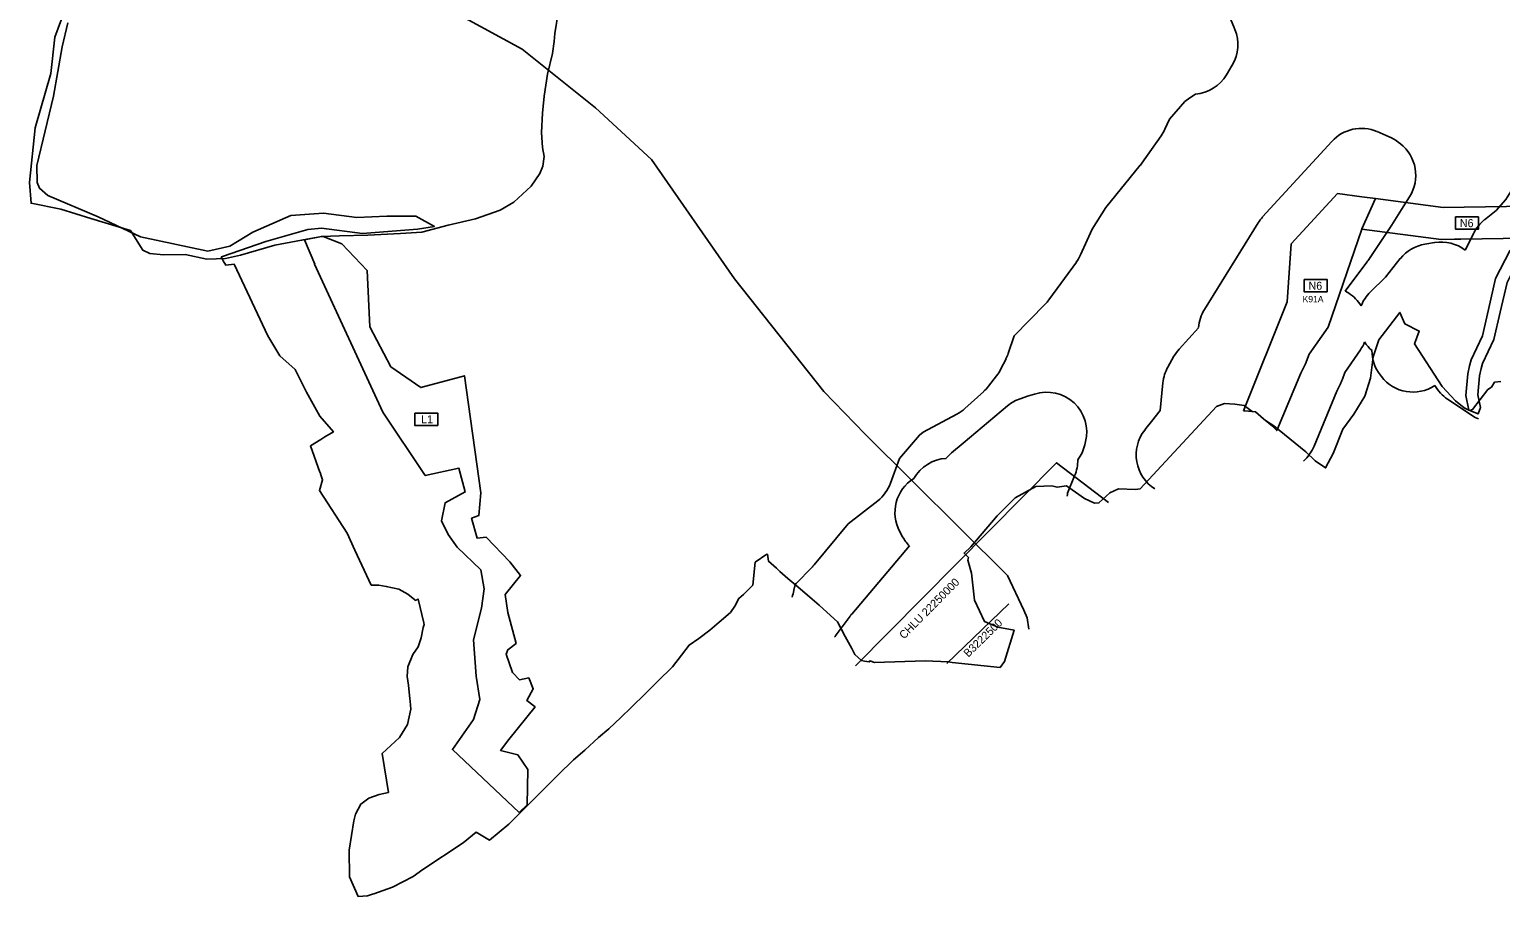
# Model space of a CAD drawing. Extents: x -547623 to -532764, y -1096714 to -1086523.
# Drawn here: x -547623 to -545785, y -1096380 to -1095297 of the extents above; entities that cross this region are included whole.
import ezdxf

# ---------------------------------------------------------------- set-up
doc = ezdxf.new("R2010")
doc.units = 0
for name, color, linetype in [('Vrstva 22', 7, 'Continuous'), ('Vrstva 23', 7, 'Continuous'), ('Vrstva 25', 7, 'Continuous'), ('Vrstva 27', 7, 'Continuous'), ('Vrstva 28', 7, 'Continuous'), ('Vrstva 33', 7, 'Continuous'), ('Vrstva 36', 7, 'Continuous'), ('Vrstva 40', 7, 'Continuous'), ('Vrstva 41', 7, 'Continuous')]:
    doc.layers.add(name, color=color, linetype=linetype)

msp = doc.modelspace()

# ---------------------------------------------------------------- linework, layer by layer
at = {"layer": 'Vrstva 22'}
for points in [[(-546374.7, -1096045.9), (-546376.9, -1096031.7), (-546380.9, -1096022.4), (-546401.2, -1095979), (-546579.1, -1095802.5), (-546630.7, -1095748.9), (-546742.6, -1095608.3), (-546846, -1095459), (-546916.2, -1095394.5), (-547007.9, -1095321.1), (-547083.5, -1095279.9), (-547200.4, -1095263.8), (-547344.8, -1095240.9), (-547527.1, -1095243.1), (-547535, -1095243.2), (-547551.1, -1095243.9), (-547564.5, -1095244.5), (-547572, -1095244.8), (-547573.4, -1095244.8)], [(-547575.4, -1095288.3), (-547582.5, -1095318.3), (-547593.3, -1095380.2), (-547614, -1095466.7), (-547613.8, -1095487.8), (-547610.9, -1095495.1), (-547600.3, -1095504.3), (-547537.7, -1095530.8), (-547484.6, -1095555.9), (-547400.5, -1095573.6), (-547373.2, -1095567.5), (-547344.1, -1095549.8), (-547296.7, -1095529.3), (-547256, -1095526.1), (-547214.4, -1095531.5), (-547177, -1095529.9), (-547140.8, -1095529.9), (-547117.3, -1095542.8), (-547138.4, -1095546.2), (-547207.2, -1095551.5), (-547258.4, -1095545.1), (-547275.6, -1095546.8), (-547328, -1095561.5), (-547382.2, -1095580.3), (-547383.7, -1095580.9), (-547381.2, -1095585.7), (-547378, -1095591.3), (-547367.7, -1095589.8), (-547325.4, -1095679.6), (-547310.7, -1095704.4), (-547291.2, -1095721.7), (-547277.2, -1095749.8), (-547260.6, -1095779.7), (-547243.6, -1095799.5), (-547254.2, -1095805.9), (-547259.2, -1095809), (-547272.4, -1095817), (-547260.6, -1095849.7), (-547259.5, -1095851.5), (-547259.8, -1095851.9), (-547257.1, -1095859.5), (-547261.1, -1095872.9), (-547226.5, -1095925.9), (-547217, -1095947.4), (-547196.4, -1095990.9), (-547186.8, -1095991.2), (-547177.5, -1095992.7), (-547162, -1095995.9), (-547150.5, -1096002.1), (-547141.9, -1096009.2), (-547141.4, -1096010.1), (-547137.7, -1096008.4), (-547130.5, -1096038.3), (-547130.5, -1096038.5), (-547130, -1096040.2), (-547131.5, -1096043.9), (-547133.9, -1096056.9), (-547137.8, -1096067.9), (-547144.5, -1096077.5), (-547150.5, -1096093.1), (-547151.4, -1096105), (-547149.9, -1096115.8), (-547148.1, -1096133), (-547147.5, -1096135.5), (-547147.8, -1096136), (-547146.7, -1096146.2), (-547151.1, -1096165.1), (-547161.2, -1096181.3), (-547182.6, -1096201.3), (-547174.8, -1096250.1), (-547186.6, -1096252.7), (-547199.2, -1096257.2), (-547209.2, -1096264.5), (-547216, -1096277.1), (-547218.1, -1096285.5), (-547223.9, -1096322.2), (-547223.7, -1096355.7), (-547212.5, -1096380.2), (-547201.1, -1096379.3), (-547194.6, -1096377.2), (-547193.1, -1096376.7), (-547169.9, -1096368.3), (-547143.8, -1096355.1), (-547131.7, -1096346.5), (-547081.4, -1096313), (-547065.1, -1096299.8), (-547048.6, -1096309.6), (-547024.3, -1096289.9), (-547015.1, -1096280.6), (-547000.8, -1096266.1), (-546979.1, -1096244.1), (-546962.9, -1096228), (-546943.7, -1096209.1), (-546929.6, -1096197.1), (-546912.2, -1096181.6), (-546899.6, -1096170.5), (-546884.6, -1096156.4), (-546871.6, -1096143.9), (-546853.8, -1096126.4), (-546838.1, -1096111.2), (-546819.9, -1096092.9), (-546808.6, -1096078.4), (-546799.2, -1096065.9), (-546787.2, -1096057.5), (-546773.2, -1096047.4), (-546761.4, -1096037.3), (-546747.4, -1096025), (-546742.2, -1096017.1), (-546737, -1096007.7), (-546731.3, -1096002.8), (-546726.2, -1095997.6), (-546719.7, -1095991.1), (-546716.8, -1095962.5), (-546702, -1095952.4), (-546702, -1095953.1), (-546701.2, -1095952.4), (-546699.8, -1095961.1), (-546690.1, -1095969.8), (-546685.7, -1095973.8), (-546675.9, -1095982.6), (-546666, -1095991.2), (-546654.6, -1096000.6), (-546645.2, -1096008.7), (-546636.7, -1096015.9), (-546626.9, -1096024.7), (-546613.9, -1096036.9), (-546604.1, -1096055.1), (-546595.8, -1096070.2), (-546592.1, -1096077.6), (-546583.8, -1096085.2), (-546580, -1096086), (-546574.1, -1096087), (-546573.5, -1096085.7), (-546567.4, -1096087.7), (-546504, -1096085.8), (-546474.9, -1096086.8), (-546470.6, -1096087.6), (-546450.5, -1096089.6), (-546410.5, -1096093.9), (-546404.9, -1096086.5), (-546393, -1096047.2), (-546413.3, -1096043.7), (-546430.1, -1096036.3), (-546442.4, -1096010), (-546446.5, -1095976.1), (-546450.7, -1095959.8), (-546450, -1095956.6), (-546455.5, -1095951), (-546447.3, -1095943.2), (-546447.3, -1095943.1), (-546414.1, -1095904.3), (-546391.6, -1095882.1), (-546366.1, -1095867.9), (-546346.1, -1095867), (-546339.4, -1095868.8), (-546327.8, -1095866.9), (-546305, -1095882.6), (-546292.6, -1095888.6), (-546287.2, -1095888.2), (-546273.4, -1095875.8), (-546262.8, -1095870.7), (-546241.5, -1095871.7), (-546235.6, -1095870.7), (-546140, -1095767.7), (-546130.1, -1095764.1), (-546117.3, -1095764.8), (-546105.7, -1095766.6), (-546095.7, -1095774.1), (-546091.3, -1095774.5), (-546081.4, -1095783), (-546078.8, -1095785.3), (-546068.7, -1095791.9), (-546028.6, -1095824.3), (-546016.7, -1095835.7), (-546003.8, -1095844.6), (-545994.6, -1095826.5), (-545982.2, -1095796), (-545968.5, -1095777.4), (-545954.7, -1095754.8), (-545947.9, -1095732.5), (-545944.6, -1095705.6), (-545937.3, -1095684.3), (-545911.1, -1095650.3), (-545905, -1095664.5), (-545886.9, -1095673.6), (-545892.7, -1095689.4), (-545858.2, -1095742.8), (-545841.6, -1095760.7), (-545830.6, -1095769.5), (-545827.4, -1095771.2), (-545823.7, -1095772.7), (-545820.2, -1095771.6), (-545801.1, -1095746.5), (-545796.7, -1095743.7), (-545793, -1095737.5), (-545784.9, -1095736.4)]]:
    msp.add_lwpolyline(points, dxfattribs=at)
at = {"layer": 'Vrstva 23'}
for p, q in [((-546127.7, -1095353.3), (-546120.5, -1095341.1)), ((-546233.4, -1095463.7), (-546209.4, -1095429.7)), ((-545996.1, -1095436.6), (-546082.5, -1095531)), ((-545924.4, -1095430.7), (-545939.6, -1095424.3)), ((-545910.4, -1095439.5), (-545913.2, -1095437.3)), ((-546088, -1095538.4), (-546155.3, -1095646.6)), ((-545950.7, -1095585.2), (-545922.3, -1095542.8)), ((-545877.3, -1095564.6), (-545879.8, -1095565)), ((-545867.6, -1095563), (-545877.2, -1095564.6)), ((-545818.6, -1095551), (-545829.3, -1095572.4)), ((-546349.7, -1095634.6), (-546315.3, -1095587.5)), ((-546162.7, -1095669.3), (-546186.9, -1095696.1)), ((-546410.1, -1095721.7), (-546403.2, -1095708.4)), ((-546193.3, -1095705), (-546201, -1095718.5)), ((-546425, -1095742.5), (-546414.9, -1095729.4)), ((-545935.4, -1095728.8), (-545934.2, -1095730.5)), ((-546454.5, -1095770.2), (-546431.1, -1095749.1)), ((-546376.2, -1095755), (-546384.4, -1095757.6)), ((-546367.5, -1095752.3), (-546376.2, -1095755)), ((-545851.6, -1095758.5), (-545820.7, -1095779.1)), ((-546304.7, -1095815.7), (-546303.8, -1095811.7)), ((-546326.4, -1095876), (-546317.5, -1095854.5)), ((-546535.8, -1095924.4), (-546532.4, -1095930.6)), ((-546523.7, -1095942.1), (-546596, -1096027.1)), ((-546665.4, -1095988.8), (-546645.8, -1095968.9)), ((-546668.1, -1095997.5), (-546666.8, -1095990.1)), ((-546598.1, -1096029.8), (-546615.4, -1096053.3)), ((-546616.8, -1096055.3), (-546617.3, -1096056))]:
    msp.add_line(p, q, dxfattribs=at)
for points in [[(-546117.2, -1095296.6), (-546118.5, -1095293.5), (-546126, -1095275.3), (-546121.3, -1095268.9)], [(-546204.6, -1095421.4), (-546199, -1095408.9), (-546179.7, -1095386.5), (-546173.7, -1095382.2), (-546166.5, -1095377.6)], [(-546310, -1095578.4), (-546295.7, -1095546.3), (-546278.3, -1095519.3), (-546235.4, -1095466.2)], [(-545753.9, -1095462.4), (-545768.1, -1095492.4), (-545778.6, -1095509), (-545790.8, -1095522.7), (-545805.2, -1095534.4)], [(-545921.5, -1095541.5), (-545909, -1095521.5), (-545899, -1095505.9)], [(-545910.5, -1095583), (-545929.2, -1095606.2), (-545948.1, -1095624.8)], [(-545975, -1095626.3), (-545979, -1095623.8), (-545979.3, -1095623.6), (-545952.2, -1095587.3)], [(-546400.3, -1095701.5), (-546393, -1095679.6), (-546354.3, -1095640.1)], [(-545982.8, -1095733.7), (-545979.9, -1095725.4), (-545960.4, -1095696.9)], [(-546207.2, -1095738.1), (-546210.7, -1095772.8), (-546221.4, -1095786.7), (-546228.3, -1095795.4), (-546229.8, -1095797.3)], [(-546018.1, -1095817.2), (-545990, -1095748.7), (-545985.4, -1095739.5)], [(-546401.5, -1095767.1), (-546456.7, -1095813.6), (-546471.2, -1095825.8)], [(-546547.5, -1095863.7), (-546536.1, -1095832.8), (-546511.4, -1095803.5), (-546506.7, -1095799.7), (-546464.5, -1095777.2)], [(-546642.9, -1095965.7), (-546600.3, -1095914.5), (-546563.5, -1095885.7)]]:
    msp.add_lwpolyline(points, dxfattribs=at)
for centre, start, end in [((-546163.5, -1095315.6), 329.3339, 22.2778), ((-546170.8, -1095327.8), 274.8993, 329.3339), ((-545959.2, -1095470.3), 66.9745, 137.5574), ((-546250.2, -1095400.8), 324.7281, 335.751), ((-545944, -1095476.8), 52.0686, 66.9745), ((-545941.2, -1095478.9), 327.4259, 52.0686), ((-546274.2, -1095434.8), 321.0365, 324.7281), ((-546045.6, -1095564.8), 137.5574, 148.1433), ((-545963.9, -1095515), 326.2197, 327.9921), ((-545773.9, -1095573.3), 128.7931, 153.4624), ((-545871.5, -1095614.3), 99.4623, 141.1731), ((-545869.1, -1095613.9), 99.3946, 99.4623), ((-545859.4, -1095612.3), 52.9674, 99.3946), ((-546355.7, -1095558), 323.8507, 335.9031), ((-545992.3, -1095557.4), 323.3168, 326.2197), ((-546390.1, -1095605.1), 315.6842, 323.8507), ((-546001.6, -1095668.7), 32.4097, 57.8301), ((-545912.9, -1095660.4), 134.6079, 158.2243), ((-546112.8, -1095673), 148.1433, 175.692), ((-546149.8, -1095729.6), 137.9221, 150.5213), ((-546001.6, -1095668.7), 325.5594, 338.2242), ((-545912.9, -1095660.4), 212.4097, 228.7237), ((-546447.7, -1095685.6), 332.8189, 341.4563), ((-545895.9, -1095698.2), 179.7572, 217.7905), ((-546454.5, -1095698.9), 322.4377, 332.8189), ((-546157.4, -1095743.1), 150.5213, 174.2499), ((-545894.7, -1095699.8), 217.7905, 303.2377), ((-546464.6, -1095712), 312.0508, 322.4377), ((-546352.3, -1095799.9), 346.3398, 107.6583), ((-546029.9, -1095716.8), 332.9792, 340.2804), ((-545823.8, -1095716.9), 209.6577, 236.2928), ((-546488, -1095733.1), 298.0424, 312.0508), ((-546369.2, -1095805.3), 107.6761, 130.1526), ((-546361, -1095802.7), 107.6583, 107.6761), ((-545793, -1095737.5), 236.2928, 246.4945), ((-546190.6, -1095828.3), 141.7032, 238.0572), ((-546353.3, -1095803.9), 322.5105, 346.3398), ((-546064.4, -1095798.3), 310.8902, 337.7348), ((-546474.9, -1095882.5), 93.4027, 150.4797), ((-546439.1, -1095864.1), 130.0137, 140.8733), ((-546363.6, -1095835.2), 337.3868, 1.0949), ((-546492, -1095900.3), 121.8827, 208.758), ((-546594.4, -1095846.3), 308.1387, 339.6598), ((-546376.4, -1095875.5), 355.1232, 359.4282), ((-546488.5, -1095906.6), 208.758, 225.3511), ((-546681.4, -1095933.8), 315.3004, 320.2433), ((-546701, -1095953.6), 313.066, 315.3004), ((-546717.4, -1095988.8), 339.7159, 349.9514), ((-546557.9, -1096059.5), 139.6045, 143.5782), ((-546575.2, -1096083), 143.5782, 146.3614)]:
    msp.add_arc(centre, 50, start, end, dxfattribs=at)
at = {"layer": 'Vrstva 25'}
msp.add_lwpolyline([(-547565.4, -1095235.1), (-547591.5, -1095306.5), (-547596.8, -1095351.7), (-547616.3, -1095419.4), (-547623.4, -1095487.8), (-547621.3, -1095513.9), (-547584, -1095521.3), (-547546.8, -1095532.9), (-547497, -1095547.9), (-547481.9, -1095572.4), (-547472.9, -1095576.5), (-547456.1, -1095578.2), (-547428.9, -1095577.9), (-547401.6, -1095583.7), (-547378.5, -1095583), (-547359.5, -1095578.5), (-547316.7, -1095566.2), (-547283.3, -1095560.1), (-547258.6, -1095555.3), (-547236, -1095554.6), (-547200.7, -1095553.9), (-547159.6, -1095551.5), (-547133.3, -1095549.8), (-547100.1, -1095541.4), (-547066.1, -1095533.4), (-547035.1, -1095522.6), (-547018.1, -1095512.3), (-546996.6, -1095492.5), (-546985.7, -1095476.8), (-546981.8, -1095467.4), (-546980.2, -1095455.4), (-546982.2, -1095444), (-546983.5, -1095425.4), (-546982.3, -1095401.3), (-546980.3, -1095380.1), (-546976.2, -1095352.7), (-546969.7, -1095326.9), (-546967.7, -1095311.8), (-546967.7, -1095311.7), (-546967.7, -1095311.7), (-546966.9, -1095301.9), (-546962.4, -1095273.3)], dxfattribs=at)
at = {"layer": 'Vrstva 27'}
msp.add_lwpolyline([(-547565.4, -1095235.1), (-547591.5, -1095306.5), (-547596.8, -1095351.7), (-547616.3, -1095419.4), (-547623.4, -1095487.8), (-547621.3, -1095513.9), (-547584, -1095521.3), (-547546.8, -1095532.9), (-547497, -1095547.9), (-547481.9, -1095572.4), (-547472.9, -1095576.5), (-547456.1, -1095578.2), (-547428.9, -1095577.9), (-547401.6, -1095583.7), (-547378.5, -1095583), (-547359.5, -1095578.5), (-547316.7, -1095566.2), (-547283.3, -1095560.1), (-547258.6, -1095555.3), (-547236, -1095554.6), (-547200.7, -1095553.9), (-547159.6, -1095551.5), (-547133.3, -1095549.8), (-547100.1, -1095541.4), (-547066.1, -1095533.4), (-547035.1, -1095522.6), (-547018.1, -1095512.3), (-546996.6, -1095492.5), (-546985.7, -1095476.8), (-546981.8, -1095467.4), (-546980.2, -1095455.4), (-546982.2, -1095444), (-546983.5, -1095425.4), (-546982.3, -1095401.3), (-546980.3, -1095380.1), (-546976.2, -1095352.7), (-546969.7, -1095326.9), (-546967.7, -1095311.8), (-546967.7, -1095311.7), (-546967.7, -1095311.7), (-546966.9, -1095301.9), (-546962.4, -1095273.3)], dxfattribs=at)
at = {"layer": 'Vrstva 28'}
for p, q in [((-545958.7, -1095505.7), (-545989, -1095501.7)), ((-546052, -1095636.9), (-546106.6, -1095773.3)), ((-546024.4, -1095702.2), (-546000.8, -1095668.6)), ((-546035, -1095726.3), (-546029, -1095714.5)), ((-546029, -1095714.5), (-546024.4, -1095702.2))]:
    msp.add_line(p, q, dxfattribs=at)
for points in [[(-545989, -1095501.7), (-546046.7, -1095564.7), (-546052, -1095636.9)], [(-546000.8, -1095668.6), (-545958.7, -1095546.1), (-545958.5, -1095545.7), (-545941.5, -1095508), (-545958.7, -1095505.7)], [(-545725, -1095516.9), (-545857.1, -1095519.2), (-545941.5, -1095508), (-545958.5, -1095545.7), (-545958.7, -1095546.1), (-545859.4, -1095559.2), (-545842.8, -1095558.9), (-545834.7, -1095558.8), (-545755.5, -1095557.4), (-545738.9, -1095539.2), (-545725, -1095516.9)], [(-546106.6, -1095773.3), (-546104.7, -1095773.2), (-546091.3, -1095774.5), (-546081.4, -1095783), (-546070.4, -1095792.5), (-546064.8, -1095797.9), (-546035, -1095726.3)]]:
    msp.add_lwpolyline(points, dxfattribs=at)
at = {"layer": 'Vrstva 33'}
for points in [[(-547279.7, -1095559.4), (-547258.6, -1095555.3)], [(-547267, -1095589.9), (-547279.7, -1095559.4)], [(-547258.6, -1095555.3), (-547256.5, -1095555.2), (-547256.3, -1095555.3), (-547233, -1095564.6), (-547201.3, -1095597.9), (-547197.9, -1095668.2), (-547171.8, -1095718.1), (-547134.4, -1095744.1), (-547080, -1095729.4), (-547059.6, -1095875.6), (-547061.9, -1095904), (-547070.9, -1095907.4), (-547064.1, -1095932.3), (-547052.8, -1095931.2), (-547023.3, -1095961.8), (-547009.7, -1095978.8), (-547029, -1096002.6), (-547025.6, -1096025.3), (-547015.4, -1096063.8), (-547025.6, -1096071.7), (-547027.9, -1096077.4), (-547019.9, -1096100.1), (-547010.9, -1096109.2), (-546999.5, -1096106.9), (-546993.9, -1096120.5), (-547001.8, -1096135.2), (-546991.6, -1096143.2), (-547024.5, -1096184), (-547034.7, -1096197.6), (-547013.1, -1096203.2), (-547000.7, -1096221.4), (-547001.5, -1096265.6), (-547011.7, -1096275.3)], [(-545825, -1095772.2), (-545828.7, -1095754.2), (-545826.2, -1095726.9), (-545823.9, -1095717), (-545822, -1095709.3), (-545808, -1095679.3), (-545800.4, -1095646.7), (-545791.4, -1095607.8), (-545773.8, -1095573.2), (-545758.8, -1095561.1), (-545755.5, -1095557.4), (-545734.9, -1095557.1), (-545748.4, -1095572), (-545761.8, -1095582.9), (-545777.2, -1095613), (-545785.8, -1095650.1), (-545793.8, -1095684.2), (-545807.8, -1095714.2), (-545809.3, -1095720.5), (-545811.4, -1095729.3), (-545813.6, -1095753.4), (-545810.3, -1095769.2), (-545813.2, -1095776.9), (-545825, -1095772.2)], [(-547011.7, -1096275.3), (-547094.8, -1096196.4), (-547068.7, -1096159), (-547060.7, -1096134.1), (-547065.3, -1096104.6), (-547068.7, -1096059.3), (-547058.5, -1096019.6), (-547055.1, -1095995.8), (-547059.6, -1095972), (-547089.1, -1095943.6), (-547100.4, -1095927.8), (-547108.4, -1095910.8), (-547103.8, -1095888.1), (-547078.9, -1095874.5), (-547086.8, -1095845), (-547128.8, -1095854.1), (-547182, -1095774.7), (-547267.1, -1095590), (-547267, -1095589.9)]]:
    msp.add_lwpolyline(points, dxfattribs=at)
at = {"layer": 'Vrstva 36'}
for points in [[(-545841.5, -1095531), (-545812.9, -1095531), (-545812.9, -1095546.4), (-545841.5, -1095546.4)], [(-546030.6, -1095609.1), (-546002, -1095609.1), (-546002, -1095624.6), (-546030.6, -1095624.6)], [(-547142, -1095776.1), (-547113.3, -1095776.1), (-547113.3, -1095791.5), (-547142, -1095791.5)]]:
    msp.add_lwpolyline(points, close=True, dxfattribs=at)
at = {"layer": 'Vrstva 40'}
msp.add_lwpolyline([(-546275.1, -1095887.8), (-546340, -1095838), (-546591.4, -1096091.7)], dxfattribs=at)
at = {"layer": 'Vrstva 41'}
msp.add_lwpolyline([(-546399.8, -1096014.2), (-546477, -1096089)], dxfattribs=at)

# ---------------------------------------------------------------- texts
at = {"layer": 'Vrstva 36'}
for s, height, p in [('N6', 10, (-545836.1, -1095543.7)), ('N6', 10, (-546025.2, -1095621.9)), ('K91A', 8, (-546032.6, -1095637.6)), ('L1', 10, (-547134, -1095788.8))]:
    msp.add_text(s, height=height, dxfattribs=at).set_placement(p)
at = {"layer": 'Vrstva 40'}
msp.add_text('CHLU 22250000', height=10, rotation=45.2823, dxfattribs=at).set_placement((-546530.6, -1096059.1))
at = {"layer": 'Vrstva 41'}
msp.add_text('B3222500', height=10, rotation=44.3163, dxfattribs=at).set_placement((-546450.4, -1096081.8))

doc.saveas('drawing.dxf')
